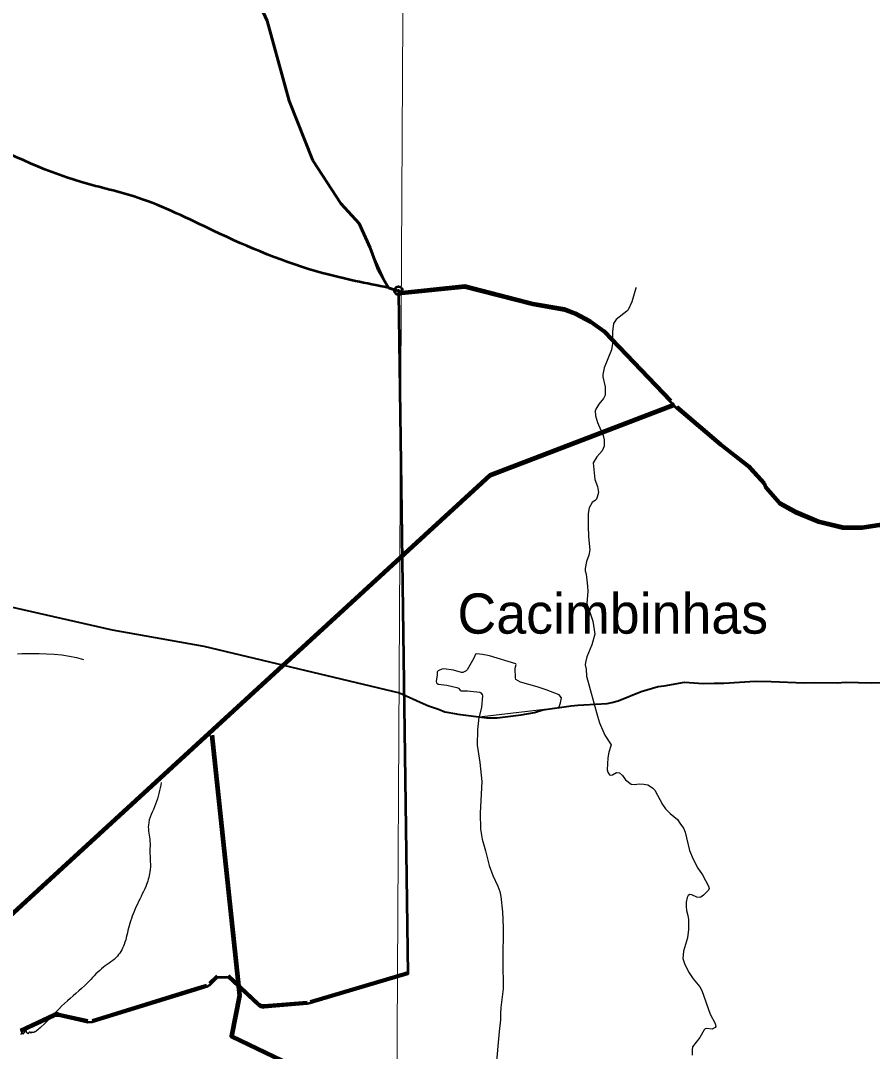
# Model space of a CAD drawing. Extents: x -1643653 to 4543381, y 1624270 to 13878484.
# Drawn here: x 714916 to 725512, y 8955698 to 8968515 of the extents above; entities that cross this region are included whole.
import ezdxf

# ---------------------------------------------------------------- set-up
doc = ezdxf.new("R2010")
doc.units = 0
doc.header["$LTSCALE"] = 200
doc.header["$PDMODE"] = 32
doc.header["$PDSIZE"] = 100
doc.linetypes.add('LONG_DASH_SHORT_DASH', pattern=[9.9, 6, -1.2, 1.5, -1.2])
for name, color, linetype, lineweight in [('1', 7, 'Continuous', 13), ('12', 7, 'Continuous', 25), ('21', 7, 'Continuous', 25), ('24', 7, 'Continuous', 25), ('58', 7, 'Continuous', 13), ('59', 7, 'Continuous', 53), ('60', 7, 'Continuous', 13), ('7', 7, 'LONG_DASH_SHORT_DASH', 60), ('9', 7, 'Continuous', 90)]:
    doc.layers.add(name, color=color, linetype=linetype, lineweight=lineweight)
doc.layers.add('41', color=7, linetype='Continuous')

msp = doc.modelspace()

# ---------------------------------------------------------------- linework, layer by layer
at = {"layer": '1'}
msp.add_lwpolyline([(719978.9, 9023574.5), (719561.6, 8949232.2), (719215.6, 8890710.6)], dxfattribs=at)
at = {"layer": '12', "lineweight": 40}
for points in [[(710551.5, 8961397.1), (711177.1, 8961501.2), (712016, 8961727.1), (712359, 8961724.2), (713550.7, 8961508.2), (716056.5, 8960938), (717193.5, 8960736.2), (719630.3, 8960157.3)], [(721922.9, 8960009), (722213.7, 8960025.4), (722269.8, 8960036.4), (722349.1, 8960058.4), (722636.1, 8960173.1), (722845.7, 8960234.4), (722922.5, 8960243.5), (723174, 8960287.2), (723408.1, 8960273.8), (723541.7, 8960277.9), (723662.4, 8960276.1), (724053.4, 8960301.3), (724251.5, 8960299.1), (724661.8, 8960282.6), (724797.4, 8960284.4), (725081.1, 8960280.5), (725171.8, 8960288.1), (725504.3, 8960282.4), (725962.1, 8960286.2), (726091.1, 8960280.3), (726144.9, 8960281.9)], [(719630.3, 8960157.3), (719924.9, 8960025), (719991.1, 8959995.2), (720116.1, 8959954.9), (720192.2, 8959919.6), (720337.5, 8959893.8), (720356.6, 8959891.3)], [(721309.9, 8959913.9), (721410.9, 8959945.9), (721766.8, 8959996.8), (721847.5, 8960004.7), (721922.9, 8960009)], [(720356.6, 8959891.3), (720717.1, 8959843.9), (720842.5, 8959844.2), (721142.7, 8959881.7), (721309.9, 8959913.9)]]:
    msp.add_lwpolyline(points, dxfattribs=at)
at = {"layer": '12'}
msp.add_lwpolyline([(720615.2, 8959855.5), (720600.9, 8959695.2), (720597, 8959505.1), (720630.5, 8959292.2), (720652.8, 8959055), (720632.1, 8958659.5), (720635, 8958462), (720656.1, 8958337.2), (720700.8, 8958191.8), (720743.2, 8958010.9), (720791.1, 8957885.8), (720852.6, 8957752.9), (720877.2, 8957688.2), (720888, 8957623.8), (720908.9, 8957434.4), (720919.8, 8957236.9), (720915.8, 8956822.8), (720917.5, 8956475.5), (720890.2, 8956243.7), (720885.8, 8956166.3), (720886.8, 8956088.9), (720868.9, 8955947.1), (720826.5, 8955484.8)], dxfattribs=at)
at = {"layer": '21'}
for points in [[(721081.2, 8960508.1), (721077.4, 8960519.1), (720747.7, 8960615.2), (720662.9, 8960634.1), (720587.2, 8960643), (720575.8, 8960636.9), (720556, 8960586.9), (720470.6, 8960443.6), (720458.9, 8960430), (720418.1, 8960410.7), (720402.2, 8960408.3), (720301.9, 8960437.2), (720181, 8960453.2), (720156.1, 8960451.2), (720109.1, 8960428.1), (720098.9, 8960418.5), (720097.9, 8960382.4), (720087.7, 8960324.8), (720086.7, 8960296.8), (720091.3, 8960280.8), (720111.5, 8960263.6), (720216.2, 8960251.9), (720344.2, 8960222.5), (720362.4, 8960214), (720382.8, 8960188), (720394.4, 8960180.7), (720474.7, 8960182.3), (720628.9, 8960163.3), (720641.9, 8960157.8), (720658.4, 8960133.9), (720662.8, 8960119.5), (720650.8, 8959977.9), (720618.4, 8959856.9), (721612.4, 8959974.7)], [(721612.4, 8959974.7), (721632.5, 8960032.7), (721644.1, 8960093.2), (721614, 8960131.4), (721452.9, 8960193.9), (721340.2, 8960231.7), (721132.5, 8960290.7), (721078, 8960323.4), (721072, 8960337.7), (721069.2, 8960462.3), (721081.2, 8960508.1)]]:
    msp.add_lwpolyline(points, dxfattribs=at)
at = {"layer": '24'}
for points in [[(722575.5, 8965195.4), (722571, 8965187.9), (722519, 8965016.7), (722474.9, 8964918.2), (722459.2, 8964901.6), (722323.5, 8964797.9), (722290.5, 8964747.2), (722279.7, 8964646.8), (722281, 8964566), (722277.5, 8964502.2), (722266.5, 8964421.5), (722176.2, 8964195.9), (722157.5, 8964115.2), (722160.4, 8964087.6), (722187, 8963962.1), (722189.1, 8963859.1), (722167.7, 8963817.5), (722110.5, 8963747.7), (722070.3, 8963681.7), (722063.8, 8963664.4), (722068.1, 8963601.1), (722094, 8963516.1), (722162.6, 8963358.1), (722176.2, 8963303.1), (722177, 8963244), (722173.6, 8963223), (722150.4, 8963167.1), (722082.2, 8963092.3), (722039.2, 8963018), (722060.5, 8962810.2), (722090.5, 8962720.7), (722103.1, 8962648.5), (722089.6, 8962588.8), (722078.8, 8962562.8), (722066.8, 8962550.6), (722025.2, 8962521.8), (721986.8, 8962458), (721978, 8962385), (721975.3, 8962231.7), (721979, 8962096), (721995.3, 8961934.2), (721985.8, 8961870.2), (721954.4, 8961789.1)], [(721954.4, 8961789.1), (721939, 8961701.5), (721940.5, 8961675.6), (721951.9, 8961632), (721968.9, 8961483.5), (721970.5, 8961415.5), (721961.3, 8961271), (721974.8, 8961199.1), (722002.5, 8961147.9), (722036.1, 8961049.7), (722059, 8960887.1), (722022.2, 8960752.4), (721958.8, 8960603.3), (721941.3, 8960535.4), (721939.8, 8960504.4), (721952, 8960451.2), (721953.6, 8960363.9)], [(714878.1, 8960643.3), (714929.4, 8960644.4), (714991.4, 8960645.3), (715064.8, 8960645.7), (715147.8, 8960645), (715237.6, 8960642.3), (715331.6, 8960636.8), (715427.3, 8960627.7), (715521.9, 8960614.1), (715612.9, 8960595.2), (715697.6, 8960570.2)], [(721953.6, 8960363.9), (722093.6, 8959865.1), (722115.4, 8959783), (722181.9, 8959629.9), (722261.1, 8959510.9)], [(722261.1, 8959510.9), (722232.9, 8959419.5), (722220.1, 8959349.1), (722211.4, 8959197.2), (722220.3, 8959168.5), (722243.5, 8959138), (722256, 8959132), (722279.2, 8959136), (722330.7, 8959164.3), (722365.7, 8959160.8), (722402.2, 8959127.6), (722442.3, 8959076.5), (722509.3, 8959021.4), (722549.7, 8959017.6), (722615.2, 8959023.5), (722670.4, 8959021.7), (722718.1, 8959012.5), (722774.8, 8958976.9), (722805.5, 8958948), (722900.4, 8958766.3), (722936.6, 8958715.7), (722995.9, 8958654.5), (723087, 8958581.5), (723116.2, 8958534.7)], [(723116.2, 8958534.7), (723162.6, 8958473.2), (723183.6, 8958425.5), (723238.3, 8958197.1), (723282.7, 8958086.6), (723342.1, 8957976.2), (723399.4, 8957895.1), (723474.7, 8957752.1), (723479.7, 8957724.8), (723473.3, 8957704.3), (723449.9, 8957676.3), (723412.8, 8957642), (723376.2, 8957617.7), (723360.7, 8957612.8), (723327.5, 8957613.9), (723266.1, 8957642.9), (723240.8, 8957648.2), (723221.2, 8957638.1), (723207.2, 8957613.1), (723195.8, 8957555.1), (723193.7, 8957499.8), (723199.5, 8957448.4), (723216.1, 8957389.2), (723224.3, 8957337.8), (723222.4, 8957215.7), (723211.1, 8957109.1), (723161.2, 8956943.2), (723155.2, 8956854.5), (723178.4, 8956777.7), (723231.8, 8956676.2), (723280.5, 8956599.2), (723364.6, 8956500.5), (723389.3, 8956454.5), (723495.1, 8956163.2), (723557.2, 8956045.2), (723565.7, 8956009), (723554.2, 8955994.3)], [(715115.4, 8955955.8), (715112.5, 8955953.5), (715108.8, 8955948.5), (715106, 8955944.2), (715100.8, 8955942.2), (715097, 8955945.6), (715092, 8955947.6), (715087.2, 8955943.3), (715082.7, 8955939), (715079.2, 8955935.2), (715074.5, 8955932.4), (715069.4, 8955931.5), (715064.5, 8955933.6), (715060.5, 8955936.7), (715056.3, 8955940.1), (715050.7, 8955937.5), (715047.4, 8955931.2), (715046.3, 8955926.1), (715040.8, 8955927.8), (715037, 8955934), (715032.6, 8955936.8), (715026.8, 8955936.8), (715021.3, 8955935.7), (715017.3, 8955932.3), (715014.2, 8955926.7), (715012.8, 8955921), (715009.1, 8955917.5), (715006.3, 8955922.5), (715000.6, 8955925.9), (714995, 8955927.9), (714991.1, 8955932.4), (714990.9, 8955937.4), (714990.6, 8955942.7), (714988.6, 8955947.8), (714985.5, 8955953.1), (714980.1, 8955951.8), (714975.4, 8955950), (714970.1, 8955953.2), (714966, 8955950), (714962.7, 8955944.2), (714962.2, 8955937.7), (714962.1, 8955931.6), (714961, 8955926.5), (714955, 8955926.5)], [(723554.2, 8955994.3), (723554.2, 8955994.3), (723519.5, 8955974.1), (723447.7, 8955984.5), (723432.7, 8955980), (723418, 8955965.8), (723364.6, 8955871.3), (723272.5, 8955754.9), (723268.2, 8955716.3), (723268.6, 8955650.3)], [(714955, 8955926.5), (714949.3, 8955929.1), (714944.7, 8955926.8), (714942.5, 8955921.3), (714946.8, 8955918.6), (714947.3, 8955913.6), (714941.8, 8955914.2), (714939.9, 8955919.7), (714937.4, 8955924.2), (714932.8, 8955927.1), (714928.7, 8955922.5), (714927.3, 8955916.6), (714923.1, 8955913), (714917.3, 8955912), (714912.5, 8955914.6)]]:
    msp.add_lwpolyline(points, dxfattribs=at)
for points in [[(716665.2, 8959042.7), (716595.1, 8958771.9), (716504.9, 8958511.2), (716524.9, 8958310.6), (716524.9, 8958190.3), (716524.9, 8957929.6), (716474.8, 8957749)], [(716474.8, 8957749), (716354.5, 8957498.3), (716264.3, 8957257.6), (716204.2, 8957027), (716103.9, 8956866.5), (715923.5, 8956726.1), (715743.1, 8956545.6), (715462.4, 8956294.9), (715171.8, 8956004.1), (715115.4, 8955955.8)]]:
    msp.add_spline(points, degree=3, dxfattribs=at)
at = {"layer": '58'}
msp.add_lwpolyline([(719491, 8965193.2), (719126.6, 8965991.5), (718899, 8966240.8), (718550, 8966774), (718255.9, 8967518.7), (717981.6, 8968510.6), (717616.1, 8969176.7), (717194.9, 8969524.6), (716647.3, 8969582.3), (715525.2, 8969298.4), (715019.8, 8969437.3), (714475, 8969813.1)], dxfattribs=at)
msp.add_spline([(712135.6, 8967581.5), (712851.5, 8967319.2), (713361.3, 8967393.4), (714238.5, 8967122.7), (715674, 8966506.4), (716373.4, 8966312.8), (717313.4, 8965902), (718673.1, 8965375), (719491, 8965193.2)], degree=3, dxfattribs=at)
at = {"layer": '59'}
for p, q in [((717267.2, 8956549.8), (717361.6, 8956643.2)), ((717500.3, 8956645), (717869.9, 8956298.7)), ((718518.3, 8956323.5), (719733.8, 8956684.8)), ((717946.5, 8956272), (718479.2, 8956316.1)), ((714915.7, 8955966.7), (715327.6, 8956159.4)), ((715327.6, 8956133.2), (714915.7, 8955940.6)), ((715391.9, 8956166.4), (715753.2, 8956085))]:
    msp.add_line(p, q, dxfattribs=at)
for points in [[(724168.2, 8962742.5), (723977.8, 8962951), (723625.8, 8963228.1), (723083.4, 8963689.1), (722178.5, 8964630.8), (722005.8, 8964757.9), (721820.1, 8964855.8), (721680.5, 8964907.3), (721288, 8964975.9), (720442, 8965194.1), (719658.3, 8965114), (719617, 8965131.1), (719733.8, 8956658.7), (718518.3, 8956297.3), (718479.2, 8956290), (717946.5, 8956245.9)], [(727272.9, 8963627.9), (726984.4, 8963163.5), (726090.3, 8962428), (725788.6, 8962257), (725386.8, 8962196.3), (725141, 8962197.3), (724841.1, 8962270), (724559.4, 8962388), (724359.5, 8962497), (724186.8, 8962696.8), (724168.2, 8962742.5)], [(717869.9, 8956272.6), (717500.3, 8956618.8), (717361.6, 8956617), (717267.2, 8956523.6), (717226.3, 8956499.2), (717087.7, 8956456.4), (715804.6, 8956060.9), (715753.2, 8956058.9), (715391.9, 8956140.2)], [(715804.6, 8956087), (717087.7, 8956482.6), (717226.3, 8956525.3)]]:
    msp.add_lwpolyline(points, dxfattribs=at)
for centre, start, end in [((717938.3, 8956371.7), 226.86813, 274.73184), ((717938.3, 8956345.5), 226.86813, 274.73184), ((715369.9, 8956068.8), 77.31474, 115.06843), ((715369.9, 8956042.6), 77.31474, 115.06843)]:
    msp.add_arc(centre, 100, start, end, dxfattribs=at)
msp.add_spline([(719491, 8965193.2), (718673.1, 8965375), (717313.4, 8965902), (716373.4, 8966312.8), (715674, 8966506.4), (714238.5, 8967122.7), (713361.3, 8967393.4), (712851.5, 8967319.2), (712135.6, 8967581.5)], degree=3, dxfattribs=at)
msp.add_point((719617, 8965157.2), dxfattribs=at)
at = {"layer": '60', "lineweight": 25}
msp.add_spline([(814781, 9009175.5), (814787.2, 9009173.4), (814796.9, 9009173.4), (814799.4, 9009172.4), (814805.1, 9009174.5), (814805.6, 9009176.5), (814811.7, 9009179.5), (814811.7, 9009179.5), (814801.5, 9009181), (814790.7, 9009181.5), (814784.1, 9009183.1), (814777.4, 9009185.1), (814778.4, 9009175.5)], degree=3, dxfattribs=at)
at = {"layer": '7'}
for points in [[(714387.4, 8969902.2), (714562.6, 8969724), (714791.2, 8969580.7), (715019.8, 8969437.3), (715266.3, 8969329.2), (715566.5, 8969291.3), (716240, 8969497.5), (716452.6, 8969548.7), (716647.3, 8969582.3), (716912.5, 8969580.1), (717194.9, 8969524.6), (717616.1, 8969176.7), (717779.5, 8968954.6), (717981.6, 8968510.6), (718255.9, 8967518.7), (718550, 8966774), (718899, 8966240.8), (719126.6, 8965991.5), (719265.4, 8965689.9), (719369.1, 8965406.3), (719491, 8965193.2), (719658.3, 8965140.1)], [(719658.3, 8965140.1), (720442, 8965220.3), (721288, 8965002.1), (721680.5, 8964933.5), (721820.1, 8964881.9), (722005.8, 8964784.1), (722178.5, 8964657), (723083.4, 8963715.2), (723625.8, 8963254.3), (723977.8, 8962977.1), (724168.2, 8962768.7), (724186.8, 8962722.9), (724359.5, 8962523.2), (724559.4, 8962414.2), (724841.1, 8962296.1), (725141, 8962223.5), (725386.8, 8962222.5), (725788.6, 8962283.2)]]:
    msp.add_lwpolyline(points, dxfattribs=at)
at = {"layer": '9'}
for points in [[(705081.2, 8958366.8), (705509.2, 8948874.2), (720755.9, 8962863.6), (723053.6, 8963740.6)], [(717295.3, 8959630.3), (717636.9, 8956393.6), (717537.2, 8955887), (718376.1, 8955487), (718808.6, 8955185.8), (719472.1, 8954177.6), (719984.6, 8952814.2), (721077.3, 8952390.4), (721486.8, 8951456.6), (721666.8, 8950799.8), (721718.4, 8950547.1), (727920.4, 8947850.3), (733274.5, 8948007.9), (737635.8, 8948628.8)]]:
    msp.add_lwpolyline(points, dxfattribs=at)

# ---------------------------------------------------------------- texts
at = {"layer": '41'}
msp.add_text('Cacimbinhas', height=500, dxfattribs=at).set_placement((720350.3, 8960892.5))

doc.saveas('drawing.dxf')
